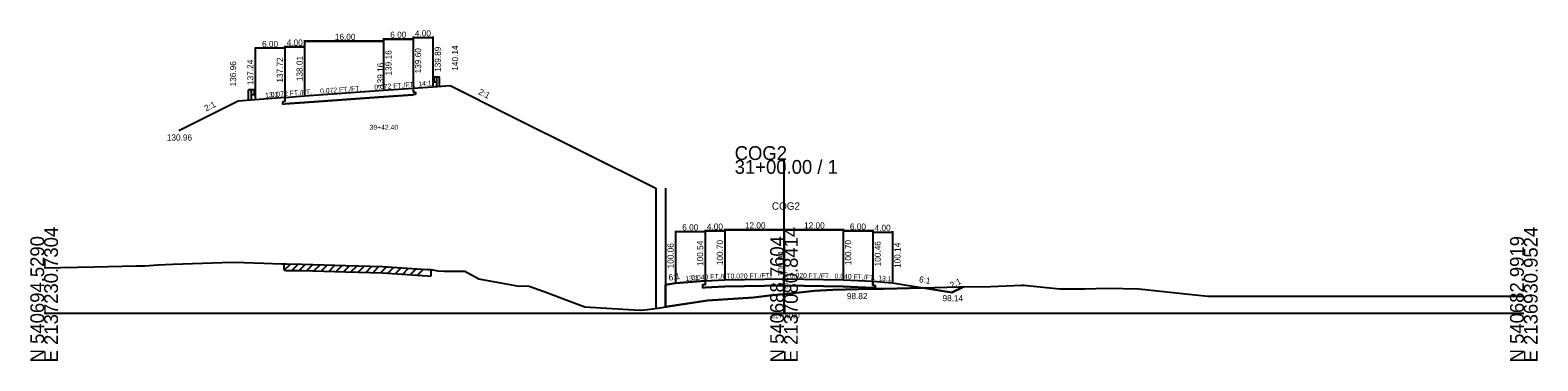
# Model space of a CAD drawing. Extents: x -13397 to 2303, y -10 to 39059.
# Drawn here: x 997.2 to 1302.8, y 1990.3 to 2057.4 of the extents above; entities that cross this region are included whole.
import ezdxf

# ---------------------------------------------------------------- set-up
doc = ezdxf.new("R2010")
doc.units = 0
for name, color, linetype in [('Level 20', 7, 'Continuous'), ('Level 5', 7, 'Continuous'), ('Level 53', 7, 'Continuous'), ('Level 54', 7, 'Continuous'), ('Level 55', 7, 'Continuous'), ('Level 7', 7, 'Continuous'), ('RD_GPK_XS_Cell', 7, 'Continuous'), ('RD_XS_EwShp', 7, 'Continuous'), ('RD_XS_ExGround', 7, 'Continuous'), ('RD_XS_ExPaveRet', 7, 'Continuous'), ('RD_XS_MedBWall', 7, 'Continuous'), ('RD_XS_Pave', 7, 'Continuous'), ('RD_XS_TX_Baseline', 7, 'Continuous'), ('RD_XS_TX_Elev_EX', 7, 'Continuous'), ('RD_XS_TX_Elev_PR', 7, 'Continuous'), ('RD_XS_TX_Station', 7, 'Continuous')]:
    doc.layers.add(name, color=color, linetype=linetype)

msp = doc.modelspace()

# ---------------------------------------------------------------- linework, layer by layer
at = {"layer": 'Level 20'}
for p, q in [((1052.8, 2055.31), (1052.8, 2044.21)), ((1052.8, 2055.31), (1052.8, 2044.21)), ((1052.8, 2055.31), (1052.8, 2044.21)), ((1052.8, 2055.31), (1052.8, 2044.21)), ((1052.8, 2055.11), (1068.8, 2055.11)), ((1052.8, 2055.11), (1068.8, 2055.11)), ((1068.8, 2055.11), (1052.8, 2055.11)), ((1068.8, 2055.11), (1052.8, 2055.11)), ((1068.8, 2055.75), (1068.8, 2045.36)), ((1068.8, 2055.75), (1068.8, 2045.36)), ((1068.8, 2055.75), (1068.8, 2045.36)), ((1068.8, 2055.55), (1074.8, 2055.55)), ((1074.8, 2055.55), (1068.8, 2055.55)), ((1074.8, 2055.55), (1068.8, 2055.55)), ((1068.8, 2055.31), (1068.8, 2045.36)), ((1068.8, 2055.31), (1068.8, 2045.36)), ((1068.8, 2055.31), (1068.8, 2045.36)), ((1068.8, 2055.31), (1068.8, 2045.36)), ((1074.8, 2056.04), (1074.8, 2045.8)), ((1074.8, 2055.84), (1078.8, 2055.84)), ((1074.8, 2055.75), (1074.8, 2045.8)), ((1074.8, 2055.75), (1074.8, 2045.8)), ((1074.8, 2055.75), (1074.8, 2045.8)), ((1078.8, 2056.04), (1078.8, 2046.09)), ((1042.8, 2053.87), (1042.8, 2043.44)), ((1048.8, 2053.67), (1042.8, 2053.67)), ((1048.8, 2054.16), (1048.8, 2043.92)), ((1048.8, 2054.16), (1048.8, 2043.92)), ((1048.8, 2054.16), (1048.8, 2043.92)), ((1048.8, 2053.96), (1052.8, 2053.96)), ((1048.8, 2053.96), (1052.8, 2053.96)), ((1052.8, 2053.96), (1048.8, 2053.96)), ((1048.8, 2053.87), (1048.8, 2043.92)), ((1052.8, 2054.16), (1052.8, 2044.21)), ((1052.8, 2054.16), (1052.8, 2044.21)), ((1052.8, 2054.16), (1052.8, 2044.21)), ((1041.46, 2043.24), (1041.46, 2045.23)), ((1042.02, 2045.23), (1041.46, 2045.23)), ((1042.02, 2043.24), (1042.02, 2045.23)), ((1042.57, 2045.23), (1042.02, 2045.23)), ((1042.57, 2045.23), (1042.57, 2044.26)), ((1042.65, 2045.15), (1042.57, 2045.17)), ((1042.77, 2045.06), (1042.66, 2045.15)), ((1052.8, 2044.01), (1068.8, 2045.16)), ((1068.8, 2045.16), (1074.8, 2045.6)), ((1074.8, 2045.6), (1078.8, 2045.89)), ((1074.8, 2045.6), (1074.8, 2044.76)), ((1078.8, 2045.89), (1082.3, 2046.14)), ((1078.83, 2047.7), (1078.94, 2047.79)), ((1078.83, 2047.6), (1078.94, 2047.51)), ((1078.83, 2047.17), (1078.94, 2047.26)), ((1078.83, 2047.07), (1078.94, 2046.98)), ((1078.96, 2047.8), (1079.03, 2047.81)), ((1078.96, 2047.46), (1078.96, 2047.31)), ((1078.96, 2046.97), (1079.03, 2046.96)), ((1079.03, 2047.87), (1079.03, 2046.9)), ((1079.03, 2047.87), (1079.58, 2047.87)), ((1079.03, 2046.9), (1079.58, 2046.9)), ((1079.58, 2045.89), (1079.58, 2047.87)), ((1079.58, 2047.87), (1080.14, 2047.87)), ((1080.14, 2045.89), (1080.14, 2047.87)), ((1082.3, 2046.14), (1094.3, 2040.14)), ((1039.3, 2042.96), (1027.3, 2036.96)), ((1042.8, 2043.24), (1039.3, 2042.96)), ((1042.57, 2044.26), (1042.02, 2044.26)), ((1042.65, 2044.33), (1042.57, 2044.32)), ((1042.64, 2044.82), (1042.64, 2044.66)), ((1042.77, 2044.96), (1042.66, 2044.86)), ((1042.77, 2044.53), (1042.66, 2044.62)), ((1042.77, 2044.43), (1042.66, 2044.33)), ((1048.8, 2043.72), (1042.8, 2043.24)), ((1048.8, 2042.89), (1048.3, 2042.85)), ((1048.3, 2042.85), (1048.3, 2042.35)), ((1048.3, 2042.35), (1048.8, 2042.39)), ((1048.8, 2043.72), (1052.8, 2044.01)), ((1048.8, 2043.72), (1048.8, 2042.89)), ((1052.8, 2042.68), (1048.8, 2042.39)), ((1052.8, 2042.68), (1048.8, 2042.39)), ((1048.8, 2042.39), (1052.8, 2042.68)), ((1068.8, 2043.83), (1052.8, 2042.68)), ((1068.8, 2043.83), (1052.8, 2042.68)), ((1052.8, 2042.68), (1068.8, 2043.83)), ((1052.8, 2042.68), (1068.8, 2043.83)), ((1074.8, 2044.26), (1068.8, 2043.83)), ((1068.8, 2043.83), (1074.8, 2044.26)), ((1068.8, 2043.83), (1074.8, 2044.26)), ((1074.8, 2044.76), (1075.3, 2044.8)), ((1075.3, 2044.3), (1074.8, 2044.26)), ((1075.3, 2044.8), (1075.3, 2044.3)), ((1094.3, 2040.14), (1124, 2025.29))]:
    msp.add_line(p, q, dxfattribs=at)
for centre, radius, start, end in [((1042.65, 2045.13), 0.026, 50.9495, 90), ((1042.73, 2045.01), 0.0651, 309.0337, 50.9664), ((1078.87, 2047.65), 0.0651, 129.0336, 230.9663), ((1078.87, 2047.12), 0.0651, 129.0336, 230.9663), ((1078.89, 2047.31), 0.0651, 302.9895, 0), ((1078.96, 2047.77), 0.026, 90, 129.0505), ((1078.89, 2047.46), 0.0651, 0, 45), ((1078.96, 2047), 0.026, 230.9496, 270), ((1042.71, 2044.82), 0.0651, 135, 180), ((1042.71, 2044.66), 0.0651, 180, 237.0105), ((1042.65, 2044.35), 0.026, 270, 309.0504), ((1042.73, 2044.48), 0.0651, 309.0337, 50.9664)]:
    msp.add_arc(centre, radius, start, end, dxfattribs=at)
at = {"layer": 'Level 5'}
for p, q in [((1134, 2005.71), (1133.5, 2005.69)), ((1133.5, 2005.69), (1133.5, 2005.19)), ((1134, 2006.54), (1134, 2005.71)), ((1138, 2005.37), (1134, 2005.21)), ((1138, 2005.37), (1134, 2005.21)), ((1138, 2005.37), (1134, 2005.21)), ((1134, 2005.21), (1138, 2005.37)), ((1150, 2005.61), (1138, 2005.37)), ((1150, 2005.61), (1138, 2005.37)), ((1150, 2005.61), (1138, 2005.37)), ((1138, 2005.37), (1150, 2005.61)), ((1138, 2005.37), (1150, 2005.61)), ((1162, 2005.37), (1150, 2005.61)), ((1162, 2005.37), (1150, 2005.61)), ((1150, 2005.61), (1162, 2005.37)), ((1150, 2005.61), (1162, 2005.37)), ((1150, 2005.61), (1162, 2005.37)), ((1168, 2005.13), (1162, 2005.37)), ((1162, 2005.37), (1168, 2005.13)), ((1162, 2005.37), (1168, 2005.13)), ((1162, 2005.37), (1168, 2005.13)), ((1168, 2006.46), (1168, 2005.63)), ((1168, 2005.63), (1168.5, 2005.61)), ((1168.5, 2005.61), (1168.5, 2005.11)), ((1133.5, 2005.19), (1134, 2005.21)), ((1168.5, 2005.11), (1168, 2005.13))]:
    msp.add_line(p, q, dxfattribs=at)
at = {"layer": 'Level 54'}
for p, q in [((1128, 2016.69), (1128, 2006.26)), ((1134, 2016.49), (1128, 2016.49)), ((1134, 2016.85), (1134, 2006.74)), ((1134, 2016.85), (1134, 2006.74)), ((1134, 2016.85), (1134, 2006.74)), ((1134, 2016.85), (1134, 2006.74)), ((1134, 2016.69), (1134, 2006.74)), ((1134, 2016.65), (1138, 2016.65)), ((1134, 2016.65), (1138, 2016.65)), ((1134, 2016.65), (1138, 2016.65)), ((1138, 2016.65), (1134, 2016.65)), ((1138, 2017.09), (1138, 2006.9)), ((1138, 2017.09), (1138, 2006.9)), ((1138, 2017.09), (1138, 2006.9)), ((1138, 2017.09), (1138, 2006.9)), ((1138, 2017.09), (1138, 2006.9)), ((1138, 2016.89), (1150, 2016.89)), ((1138, 2016.89), (1150, 2016.89)), ((1138, 2016.89), (1150, 2016.89)), ((1150, 2016.89), (1138, 2016.89)), ((1150, 2016.89), (1138, 2016.89)), ((1138, 2016.85), (1138, 2006.9)), ((1138, 2016.85), (1138, 2006.9)), ((1138, 2016.85), (1138, 2006.9)), ((1138, 2016.85), (1138, 2006.9)), ((1150, 2017.09), (1150, 2007.14)), ((1150, 2017.09), (1150, 2007.14)), ((1150, 2017.09), (1150, 2007.14)), ((1150, 2017.09), (1150, 2007.14)), ((1150, 2017.09), (1150, 2007.14)), ((1150, 2017.09), (1150, 2007.14)), ((1150, 2017.09), (1150, 2007.14)), ((1150, 2017.09), (1150, 2007.14)), ((1150, 2017.09), (1150, 2007.14)), ((1150, 2017.09), (1150, 2007.14)), ((1150, 2016.89), (1162, 2016.89)), ((1150, 2016.89), (1162, 2016.89)), ((1162, 2016.89), (1150, 2016.89)), ((1162, 2016.89), (1150, 2016.89)), ((1162, 2016.89), (1150, 2016.89)), ((1162, 2017.09), (1162, 2006.9)), ((1162, 2017.09), (1162, 2006.9)), ((1162, 2017.09), (1162, 2006.9)), ((1162, 2017.09), (1162, 2006.9)), ((1162, 2017.09), (1162, 2006.9)), ((1162, 2016.85), (1162, 2006.9)), ((1162, 2016.85), (1162, 2006.9)), ((1162, 2016.85), (1162, 2006.9)), ((1162, 2016.85), (1162, 2006.9)), ((1162, 2016.65), (1168, 2016.65)), ((1168, 2016.65), (1162, 2016.65)), ((1168, 2016.65), (1162, 2016.65)), ((1168, 2016.65), (1162, 2016.65)), ((1168, 2016.85), (1168, 2006.66)), ((1168, 2016.85), (1168, 2006.66)), ((1168, 2016.85), (1168, 2006.66)), ((1168, 2016.85), (1168, 2006.66)), ((1168, 2016.61), (1168, 2006.66)), ((1168, 2016.41), (1172, 2016.41)), ((1172, 2016.61), (1172, 2006.34))]:
    msp.add_line(p, q, dxfattribs=at)
at = {"layer": 'Level 7'}
for p, q in [((1128, 2006.06), (1126, 2005.73)), ((1126, 2005.73), (1126, 2001.26)), ((1134, 2006.54), (1128, 2006.06)), ((1168, 2006.46), (1172, 2006.14)), ((1172, 2006.14), (1184, 2004.14)), ((1184, 2004.14), (1186.37, 2005.33))]:
    msp.add_line(p, q, dxfattribs=at)
at = {"layer": 'RD_GPK_XS_Cell'}
for p, q in [((1150, 2000), (1150, 2031.03)), ((1000, 2000), (1150, 2000)), ((1150, 2000), (1300, 2000))]:
    msp.add_line(p, q, dxfattribs=at)
at = {"layer": 'RD_XS_EwShp'}
for points in [[(1134, 2005.71), (1133.5, 2005.69), (1133.5, 2005.19), (1134, 2005.21), (1138, 2005.37), (1150, 2005.61), (1162, 2005.37), (1168, 2005.13), (1168.5, 2005.11), (1168.5, 2005.61), (1168, 2005.63), (1168, 2006.46), (1172, 2006.14), (1178.15, 2005.11), (1170.33, 2004.94), (1167.6, 2004.89), (1159.88, 2004.69), (1156.16, 2004.48), (1150, 2003.86), (1147.09, 2003.57), (1143.81, 2003.17), (1134.48, 2002.54), (1126, 2001.26), (1126, 2005.73), (1128, 2006.06), (1134, 2006.54)], [(1183.11, 2005.23), (1185.44, 2005.32), (1186.37, 2005.33), (1184, 2004.14), (1178.15, 2005.11)]]:
    msp.add_lwpolyline(points, close=True, dxfattribs=at)
at = {"layer": 'RD_XS_ExGround'}
for p, q in [((1000, 2009.14), (1010.18, 2009.36)), ((1010.18, 2009.36), (1018.67, 2009.56)), ((1018.67, 2009.56), (1019.75, 2009.54)), ((1019.75, 2009.54), (1020.38, 2009.56)), ((1020.38, 2009.56), (1023.06, 2009.74)), ((1023.06, 2009.74), (1026.11, 2009.9)), ((1026.11, 2009.9), (1036.07, 2010.28)), ((1036.07, 2010.28), (1038.55, 2010.34)), ((1038.55, 2010.34), (1044.51, 2010.12)), ((1044.51, 2010.12), (1048.11, 2009.96)), ((1048.11, 2009.96), (1048.69, 2009.96)), ((1048.69, 2009.96), (1049.08, 2009.95)), ((1049.08, 2009.95), (1052.25, 2009.9)), ((1052.25, 2009.9), (1061.18, 2009.65)), ((1061.18, 2009.65), (1068.61, 2009.45)), ((1068.61, 2009.45), (1075.59, 2008.98)), ((1075.59, 2008.98), (1077.7, 2008.81)), ((1077.7, 2008.81), (1078.4, 2008.8)), ((1078.4, 2008.8), (1079.83, 2008.59)), ((1079.83, 2008.59), (1081.13, 2008.46)), ((1081.13, 2008.46), (1082.31, 2008.52)), ((1082.31, 2008.52), (1085.29, 2008.46)), ((1085.29, 2008.46), (1088.11, 2006.92)), ((1088.11, 2006.92), (1088.82, 2006.77)), ((1088.82, 2006.77), (1096.24, 2005.42)), ((1096.24, 2005.42), (1097.38, 2005.52)), ((1097.38, 2005.52), (1098.35, 2005.48)), ((1098.35, 2005.48), (1101.15, 2004.46)), ((1183.11, 2005.23), (1185.44, 2005.32)), ((1185.44, 2005.32), (1191.85, 2005.38)), ((1191.85, 2005.38), (1198.23, 2005.63)), ((1198.23, 2005.63), (1198.68, 2005.65)), ((1198.68, 2005.65), (1199.26, 2005.61)), ((1199.26, 2005.61), (1205.92, 2004.88)), ((1101.15, 2004.46), (1109.64, 2001.27)), ((1123.9, 2000.94), (1134.48, 2002.54)), ((1134.48, 2002.54), (1143.81, 2003.17)), ((1143.81, 2003.17), (1147.09, 2003.57)), ((1147.09, 2003.57), (1150, 2003.86)), ((1150, 2003.86), (1156.16, 2004.48)), ((1156.16, 2004.48), (1159.88, 2004.69)), ((1159.88, 2004.69), (1167.6, 2004.89)), ((1167.6, 2004.89), (1170.33, 2004.94)), ((1170.33, 2004.94), (1183.11, 2005.23)), ((1205.92, 2004.88), (1211.01, 2004.91)), ((1211.01, 2004.91), (1215.49, 2005.06)), ((1215.49, 2005.06), (1221.95, 2004.92)), ((1221.95, 2004.92), (1227.59, 2004.32)), ((1227.59, 2004.32), (1235.91, 2003.44)), ((1235.91, 2003.44), (1237.86, 2003.44)), ((1237.86, 2003.44), (1245.6, 2003.44)), ((1245.6, 2003.44), (1246.36, 2003.44)), ((1246.36, 2003.44), (1248.02, 2003.44)), ((1248.02, 2003.44), (1250.71, 2003.44)), ((1250.71, 2003.44), (1283.14, 2003.44)), ((1283.14, 2003.44), (1289.17, 2003.44)), ((1289.17, 2003.44), (1291.15, 2003.44)), ((1291.15, 2003.44), (1300, 2003.44)), ((1109.64, 2001.27), (1119.6, 2000.62)), ((1119.6, 2000.62), (1120.99, 2000.57)), ((1120.99, 2000.57), (1121.76, 2000.66)), ((1121.76, 2000.66), (1123.9, 2000.94))]:
    msp.add_line(p, q, dxfattribs=at)
at = {"layer": 'RD_XS_ExPaveRet'}
for p, q in [((1048.69, 2008.66), (1048.69, 2009.96)), ((1048.69, 2008.66), (1049.97, 2009.94)), ((1048.69, 2008.66), (1049.08, 2008.65)), ((1049.08, 2008.65), (1052.25, 2008.6)), ((1050.19, 2008.63), (1051.47, 2009.91)), ((1051.69, 2008.61), (1052.96, 2009.88)), ((1052.25, 2008.6), (1061.18, 2008.35)), ((1053.19, 2008.57), (1054.45, 2009.84)), ((1054.69, 2008.53), (1055.95, 2009.8)), ((1056.19, 2008.49), (1057.45, 2009.76)), ((1057.69, 2008.45), (1058.95, 2009.71)), ((1059.19, 2008.41), (1060.45, 2009.67)), ((1060.69, 2008.37), (1061.95, 2009.63)), ((1061.18, 2008.35), (1068.61, 2008.15)), ((1062.19, 2008.33), (1063.45, 2009.59)), ((1063.69, 2008.29), (1064.95, 2009.55)), ((1065.19, 2008.25), (1066.45, 2009.51)), ((1066.69, 2008.21), (1067.95, 2009.47)), ((1068.19, 2008.17), (1069.42, 2009.4)), ((1069.69, 2008.08), (1070.9, 2009.3)), ((1071.19, 2007.98), (1072.4, 2009.19)), ((1072.69, 2007.87), (1073.9, 2009.09)), ((1074.19, 2007.77), (1075.4, 2008.99)), ((1075.69, 2007.67), (1076.89, 2008.87)), ((1078.4, 2008.8), (1078.4, 2007.5)), ((1068.61, 2008.15), (1075.59, 2007.68)), ((1075.59, 2007.68), (1077.7, 2007.51)), ((1077.7, 2007.51), (1078.4, 2007.5))]:
    msp.add_line(p, q, dxfattribs=at)
at = {"layer": 'RD_XS_MedBWall'}
for p, q in [((1124, 2025.29), (1124, 2000.96)), ((1126, 2025.29), (1126, 2005.73))]:
    msp.add_line(p, q, dxfattribs=at)
at = {"layer": 'RD_XS_Pave'}
for p, q in [((1134, 2006.54), (1138, 2006.7)), ((1138, 2006.7), (1150, 2006.94)), ((1150, 2006.94), (1162, 2006.7)), ((1162, 2006.7), (1168, 2006.46))]:
    msp.add_line(p, q, dxfattribs=at)

# ---------------------------------------------------------------- texts
at = {"layer": 'Level 20'}
for s, height, p in [('4.00', 1.25, (1075.17, 2056.09)), ('6.00', 1.25, (1044.17, 2053.92)), ('4.00', 1.25, (1049.17, 2054.21)), ('4.00', 1.25, (1049.17, 2054.21)), ('4.00', 1.25, (1049.17, 2054.21)), ('16.00', 1.25, (1058.93, 2055.36)), ('16.00', 1.25, (1058.93, 2055.36)), ('16.00', 1.25, (1058.93, 2055.36)), ('16.00', 1.25, (1058.93, 2055.36)), ('6.00', 1.25, (1070.17, 2055.8)), ('6.00', 1.25, (1070.17, 2055.8)), ('6.00', 1.25, (1070.17, 2055.8)), ('130.96', 1.25, (1024.87, 2034.96)), ('39+42.40', 1, (1065.97, 2037.16))]:
    msp.add_text(s, height=height, dxfattribs=at).set_placement(p)
for s, height, rotation, p in [('140.14', 1.25, 90, (1083.93, 2049.14)), ('137.24', 1.25, 90, (1042.42, 2046.24)), ('137.72', 1.25, 90, (1048.42, 2046.72)), ('138.01', 1.25, 90, (1052.42, 2047.01)), ('138.01', 1.25, 90, (1052.42, 2047.01)), ('139.16', 1.25, 90, (1070.43, 2048.16)), ('139.16', 1.25, 90, (1070.43, 2048.16)), ('139.60', 1.25, 90, (1076.43, 2048.6)), ('139.89', 1.25, 90, (1080.43, 2048.89)), ('136.96', 1.25, 90, (1038.92, 2045.96)), (' 139.16', 1.25, 90, (1068.8, 2045.16)), ('0.072 FT./FT.', 1, 4.1284, (1045.98, 2043.77)), ('0.072 FT./FT.', 1, 4.1284, (1045.98, 2043.77)), ('0.072 FT./FT.', 1, 4.1284, (1045.98, 2043.77)), ('0.072 FT./FT.', 1, 4.1283, (1055.98, 2044.49)), ('0.072 FT./FT.', 1, 4.1283, (1055.98, 2044.49)), ('0.072 FT./FT.', 1, 4.1283, (1055.98, 2044.49)), ('0.072 FT./FT.', 1, 4.1283, (1055.98, 2044.49)), ('0.072 FT./FT.', 1, 4.1281, (1066.98, 2045.28)), ('0.072 FT./FT.', 1, 4.1281, (1066.98, 2045.28)), ('0.072 FT./FT.', 1, 4.1281, (1066.98, 2045.28)), ('14:1', 1, 4.1275, (1075.89, 2045.93)), ('2:1', 1.25, 333.4378, (1087.91, 2044.45)), ('2:1', 1.25, 26.562, (1032.85, 2040.85)), ('13:1', 1, 4.5733, (1044.83, 2043.65))]:
    msp.add_text(s, height=height, rotation=rotation, dxfattribs=at).set_placement(p)
at = {"layer": 'Level 53'}
for s, rotation, p in [('100.54', 90, (1133.62, 2009.54)), ('100.70', 90, (1137.62, 2009.7)), ('100.70', 90, (1137.62, 2009.7)), ('100.70', 90, (1137.62, 2009.7)), ('100.70', 90, (1163.62, 2009.7)), ('100.70', 90, (1163.62, 2009.7)), ('100.70', 90, (1163.62, 2009.7)), ('100.46', 90, (1169.62, 2009.46)), ('100.06', 90, (1127.62, 2009.06)), ('100.14', 90, (1173.62, 2009.14)), ('6:1', 9.4623, (1126.69, 2006.54)), ('6:1', 350.5377, (1177.3, 2006.27))]:
    msp.add_text(s, height=1.25, rotation=rotation, dxfattribs=at).set_placement(p)
for s, p in [('98.82', (1162.75, 2002.82)), ('98.14', (1182.14, 2002.39))]:
    msp.add_text(s, height=1.25, dxfattribs=at).set_placement(p)
at = {"layer": 'Level 54'}
for s, p in [('6.00', (1129.37, 2016.74)), ('4.00', (1134.37, 2016.9)), ('4.00', (1134.37, 2016.9)), ('4.00', (1134.37, 2016.9)), ('4.00', (1134.37, 2016.9)), ('12.00', (1142.07, 2017.14)), ('12.00', (1142.07, 2017.14)), ('12.00', (1142.07, 2017.14)), ('12.00', (1142.07, 2017.14)), ('12.00', (1142.07, 2017.14)), ('12.00', (1154.07, 2017.14)), ('12.00', (1154.07, 2017.14)), ('12.00', (1154.07, 2017.14)), ('12.00', (1154.07, 2017.14)), ('12.00', (1154.07, 2017.14)), ('6.00', (1163.37, 2016.9)), ('6.00', (1163.37, 2016.9)), ('6.00', (1163.37, 2016.9)), ('6.00', (1163.37, 2016.9)), ('4.00', (1168.37, 2016.66))]:
    msp.add_text(s, height=1.25, dxfattribs=at).set_placement(p)
at = {"layer": 'Level 55'}
for s, height, rotation, p in [('13:1', 1, 4.5739, (1130.03, 2006.47)), ('0.040 FT./FT.', 1, 2.2906, (1131.22, 2006.68)), ('0.040 FT./FT.', 1, 2.2906, (1131.22, 2006.68)), ('0.040 FT./FT.', 1, 2.2906, (1131.22, 2006.68)), ('0.040 FT./FT.', 1, 2.2906, (1131.22, 2006.68)), ('0.020 FT./FT.', 1, 1.1458, (1139.17, 2006.97)), ('0.020 FT./FT.', 1, 1.1458, (1139.17, 2006.97)), ('0.020 FT./FT.', 1, 1.1458, (1139.17, 2006.97)), ('0.020 FT./FT.', 1, 1.1458, (1139.17, 2006.97)), ('0.020 FT./FT.', 1, 1.1458, (1139.17, 2006.97)), ('0.020 FT./FT.', 1, 358.8542, (1151.18, 2007.17)), ('0.020 FT./FT.', 1, 358.8542, (1151.18, 2007.17)), ('0.020 FT./FT.', 1, 358.8542, (1151.18, 2007.17)), ('0.020 FT./FT.', 1, 358.8542, (1151.18, 2007.17)), ('0.020 FT./FT.', 1, 358.8542, (1151.18, 2007.17)), ('0.040 FT./FT.', 1, 357.7094, (1160.24, 2007.02)), ('0.040 FT./FT.', 1, 357.7094, (1160.24, 2007.02)), ('0.040 FT./FT.', 1, 357.7094, (1160.24, 2007.02)), ('0.040 FT./FT.', 1, 357.7094, (1160.24, 2007.02)), ('13:1', 1, 355.4261, (1169.07, 2006.63)), ('2:1', 1.25, 26.5651, (1184.01, 2004.98))]:
    msp.add_text(s, height=height, rotation=rotation, dxfattribs=at).set_placement(p)
at = {"layer": 'RD_GPK_XS_Cell'}
for s, p in [('COG2', (1140, 2031.03)), ('31+00.00 / 1', (1140, 2028.23))]:
    msp.add_text(s, height=2.8, dxfattribs=at).set_placement(p)
for s, p in [('N 540694.5290', (1000, 1990)), ('E 2137230.7304', (1002.8, 1990)), ('N 540688.7604', (1150, 1990)), ('E 2137080.8414', (1152.8, 1990)), ('N 540682.9919', (1300, 1990)), ('E 2136930.9524', (1302.8, 1990))]:
    msp.add_text(s, height=2.8, rotation=90, dxfattribs=at).set_placement(p)
at = {"layer": 'RD_XS_TX_Baseline'}
msp.add_text('COG2', height=1.5, dxfattribs=at).set_placement((1147.55, 2020.94))
at = {"layer": 'RD_XS_TX_Elev_EX'}
msp.add_text('97.86', height=1, rotation=90, dxfattribs=at).set_placement((1150.75, 2004.86))
at = {"layer": 'RD_XS_TX_Elev_PR'}
msp.add_text(' 100.94', height=1.25, rotation=90, dxfattribs=at).set_placement((1150, 2006.94))
at = {"layer": 'RD_XS_TX_Station'}
msp.add_text('31+00.00', height=1, dxfattribs=at).set_placement((1147.37, 1998.94))

doc.saveas('drawing.dxf')
